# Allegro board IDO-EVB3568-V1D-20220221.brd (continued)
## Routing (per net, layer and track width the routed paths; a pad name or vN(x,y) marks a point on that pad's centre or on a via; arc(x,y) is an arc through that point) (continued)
GND_EARTH: length 535
  TOP w0.432: 136.01,89.17 J31.SH2 137.46,90.62
  GND w1.016: H2.1 9.02,0.89 94.74,0.89 96.01,2.16 100.08,2.16 101.35,0.89 135.92,0.89 H1.1 144.27,9.25 144.27,75.03 H4.1
  GND w1.524: H4.1 140.06,86.58 J31.SH2 J31.SH1 J30.SH2 J30.SH1
  BOTTOM w1.016: H2.1 9.02,0.89 94.74,0.89 96.01,2.16 100.08,2.16 101.35,0.89 135.92,0.89 H1.1 144.27,9.25 144.27,75.03 H4.1
  BOTTOM w1.524: H4.1 140.06,86.58 J31.SH2 J31.SH1 J30.SH2 J30.SH1
GND_IN: length 51.4
  TOP w0.432: 10.17,93.58 J2.2 ; J2.2 12.12,93.58 ; J2.2 11.14,95.26 ; J2.2 11.14,91.91 ; 18.19,88.21 J1.1 ; J1.1 19,87.4 ; J1.1 19.81,88.21 ; J1.1 19,89.03 ; 16.97,87.4 J1.2 ; J1.2 16.97,89.03 ; J1.2 16.15,88.21 ; J1.2 17.78,88.21 ; 4.97,93.58 J2.3 ; J2.3 5.94,95.26 ; J2.3 5.94,91.91 ; J2.3 6.92,93.58
  GND w0.432: 4.97,93.58 J2.3 ; J2.3 6.92,93.58 ; J2.3 5.94,91.91 ; J2.3 5.94,95.26 ; 16.97,87.4 J1.2 ; J1.2 16.97,89.03 ; J1.2 16.15,88.21 ; J1.2 17.78,88.21 ; 18.19,88.21 J1.1 ; J1.1 19,89.03 ; J1.1 19.81,88.21 ; J1.1 19,87.4 ; J2.2 12.12,93.58 ; J2.2 10.17,93.58 ; J2.2 11.14,91.91 ; J2.2 11.14,95.26
  BOTTOM w0.432: 16.97,87.4 J1.2 ; J1.2 17.78,88.21 ; J1.2 16.15,88.21 ; J1.2 16.97,89.03 ; 19,87.4 J1.1 ; J1.1 19.81,88.21 ; J1.1 18.19,88.21 ; J1.1 19,89.03 ; 11.14,91.91 J2.2 ; J2.2 11.14,95.26 ; J2.2 10.17,93.58 ; J2.2 12.12,93.58 ; J2.3 6.92,93.58 ; J2.3 4.97,93.58 ; J2.3 5.94,95.26 ; J2.3 5.94,91.91
  vias: v1(5.59,78.36) v1(5.59,77.6) v1(6.35,78.36) v1(6.35,77.6) v1(6.35,76.83) v1(6.35,76.07) v1(6.35,75.31) v1(7.11,77.6) v1(7.11,76.83) v1(7.11,76.07) v1(7.11,75.31) v1(7.87,77.34)
VBAT_RTC: length 15
  TOP w0.305: v1(134.11,32.82) 134.11,33.26 J40.2
  TOP w0.508: D93.A v1(123.57,37.2)
  BOTTOM w0.508: v1(134.11,32.82) 134.11,35.05 131.96,37.2 v1(123.57,37.2)
VBUSM: length 4.3
  BOTTOM w0.254: U8.41 82.13,55.89 R45.1
  BOTTOM w0.381: R44.1 R45.1
VCC1V5_DVP: length 4.9
  TOP w0.381: v2(27.05,60.07) 27.05,59.44 ; 27.05,59.44 27.15,59.44 27.58,59.87 v2(27.58,60.07) ; 27.05,59.44 26.42,58.8 J28.3 ; R388.2 C492.1 29.62,59.49 v1(29.97,59.84)
VCC1V8_DVP: length 0.9
  TOP w0.381: v1(24.77,59.64) 24.43,59.3 J28.4
VCC2V8_DVP: length 0.9
  BOTTOM w0.305: C152.2 R390.2
  vias: v2(27.3,56.26) v2(27.64,56.11) v2(27.64,55.7)
VCC3V3_PHY0: length 18.1
  TOP w0.152: R191.2 101.3,77.04 100.97,76.71 100.97,75.62 102.54,74.04 103.99,74.04 C188.2
  TOP w0.203: R196.2 v2(103.15,69.47) 103.15,69.98 R200.2
  TOP w0.381: C188.2 C187.2 104.28,72.54 v2(103.8,73.03) ; v1(110.36,73.3) C189.2 ; v1(110.36,73.3) 110.47,73.2 R218.1 ; v1(110.36,73.3) 110.54,73.48 110.82,73.48 v2(111.08,73.74)
  TOP w0.508: v2(104.97,67.74) 104.97,67.66 C190.2
  BOTTOM w0.203: 105.15,67.89 105.18,67.89 105.43,68.14 U24.29 ; 105.03,67.8 105.06,67.8
  BOTTOM w0.254: v2(104.97,67.74) 105.03,67.8 ; U24.11 109.7,72.67 110.34,73.3 v1(110.36,73.3) ; U24.40 104.16,72.67 v2(103.8,73.03)
  BOTTOM w0.305: 105.06,67.8 105.15,67.89
  BOTTOM w0.508: v1(110.36,73.3) 110.39,73.28 C191.2 v2(111.08,73.74) 111.35,74.02 111.35,74.09 R229.2
VCC3V3_PHY1: length 19.6
  TOP w0.305: C212.2 118.14,66.73 118.14,66.37 118.39,66.11 118.75,66.11
  TOP w0.381: C214.2 118.42,72.54 118.21,72.34 118.21,71.85 v2(118.11,71.75) C215.2 ; C213.2 125.64,71.66 125.64,72.2 125.63,72.21 v1(125.63,72.24) R277.2 ; C216.2 123.6,71.75 v2(123.62,71.73) 123.71,71.64 124.25,71.64 124.28,71.68 R266.1 ; R243.2 117.55,66.5 117.93,66.88 118.24,66.88 118.41,66.7 118.41,66.45 v2(118.77,66.09)
  VCC w0.203: 117.5,73.41 117.4,73.41 116.76,72.77 116.05,72.77 115.14,73.69 115.14,74.78 114.2,75.72 113.06,75.72 v2(112.93,75.59)
  BOTTOM w0.203: R247.2 112.93,74.76 v2(112.93,75.59) 112.72,75.59 R238.2 ; 118.78,66.08 v2(118.77,66.09)
  BOTTOM w0.254: v2(123.62,71.73) 123.62,71.17 123.44,70.99 U25.11 ; U25.29 119.45,66.52 119.41,66.47 119.41,66.38 119.1,66.08 119.07,66.08 ; U25.40 118.11,71.38 v2(118.11,71.75)
  BOTTOM w0.305: 119.07,66.08 118.78,66.08
VCC3V3_SD: length 49.8
  TOP w0.508: M5.69 94.67,35.24 93.34,33.91 v1(93.34,31.24) ; J3.4 125.63,16.06 125.7,16.13 D2.1 125.7,17.63 125.92,17.84 C35.2 125.92,18.73 125.41,19.24 v1(125.41,19.24)
  BOTTOM w0.508: v1(125.41,19.24) 125.41,20.13 122.68,22.86 120.02,22.86 113.67,29.21 113.67,29.84 113.16,30.35 107.31,30.35 105.92,31.75 103.25,31.75 102.36,30.86 94.36,30.86 93.98,31.24 v1(93.34,31.24)
VCC5V0_SYS: length 214.3
  TOP w0.203: R309.1 21.95,32.84 21.95,35.1 22.25,35.41 R306.1
  TOP w0.254: R13.1 C24.2 v1(26.42,53.85)
  TOP w0.381: v1(77.85,8.89) 77.85,8.08 78.21,7.72
  TOP w0.508: v1(21.34,37.47) 21.03,37.16 C236.2 20.3,36.85 19.94,37.21 U33.3 ; J34.4 10.16,60 ; R306.1 v1(22.93,35.99)
  TOP w0.762: J36.4 9.05,34.09 9.63,34.67 ; v1(75.39,52.83) 75.39,45.16 70.48,40.26 64.95,40.26 64.19,39.5 54.51,39.5 53.75,38.73 v1(53.75,38.51) ; 10.54,47.04 10.54,48.63 v1(8.88,50.29) 10.44,51.85 10.44,59.72 10.16,60 10.31,60.15 10.31,72.92 10.34,72.95 ; 10.54,47.04 J35.4 ; 10.54,47.04 10.54,39.62 10.19,39.27 ; 10.34,72.95 v1(10.59,73.2) 10.97,73.2 v1(11.3,73.53) 11.46,73.69 11.46,84.51 10.06,85.91 J32.4 ; 10.34,72.95 J33.4
  TOP w1.016: J20.3 84.04,7.72 78.21,7.72 75.95,5.46 56.64,5.46 54.36,7.75 50.29,7.75 49.34,8.7 J25.3
  BOTTOM w0.203: 48.56,35.46 48.95,35.46 49.84,34.57 R7.1
  BOTTOM w0.381: v1(84.2,19.43) 84.32,19.55 Q17.1 85.73,19.55 85.8,19.48 R380.1 ; v1(75.39,52.83) 75.9,52.32 78.74,52.32 80.01,53.59 R44.2 ; v1(73.53,12.45) 76.96,12.45 77.85,11.56 v1(77.85,8.89) ; v1(26.42,53.85) 26.42,43.48 27.36,42.55 v1(29.97,42.55)
  BOTTOM w0.508: v1(75.39,52.83) 75.39,53.53 L13.1 ; D83.A v1(8.88,50.29)
  BOTTOM w0.762: v1(11.3,73.53) 10.97,73.2 v1(10.59,73.2) ; v1(53.75,38.51) 53.7,38.51 52.81,37.62 52.81,31.72 v1(52.2,31.11)
  BOTTOM w1.016: v1(78.05,24.64) v1(78.05,22.35) 78.05,21.44 79.12,20.38 79.12,16.76 85.46,10.43 J20.3
  vias: v1(15.98,26.95) v1(16.23,27.48) v1(16.51,26.49) v1(21.08,43.31) v1(21.26,42.75) v1(21.62,43.15) v1(29.95,42.01) v1(29.95,41.48) v1(30.51,42.55) v1(30.48,42.01) v1(30.48,41.48) v1(31.04,42.55) v1(31.01,42.01) v1(31.01,41.45) v1(33.99,15.19) v1(34.52,15.16) v1(38.48,26.04) v1(38.48,25.4) v1(38.48,24.77) v1(39.06,26.08) v1(39.12,25.4) v1(39.12,24.77) v1(46.61,36.07) v1(47.12,35.31) v1(47.88,36.07) v1(47.88,35.31) v1(104.39,22.35) v2(104.27,21.72) v2(104.8,21.72) v2(110.36,39.88) v2(110.36,39.37) v2(110.87,39.88) v2(110.87,39.37) v2(111.38,39.88) v2(111.38,39.37)
VCC5V0_USB_FE_D1: length 0.8
  TOP w1.016: J8.10 73.76,87.91
VCC5V0_USB_FE_D2: length 2.7
  TOP w0.432: 91.37,91.34 J9.1 ; J9.1 92.04,92.02 ; J9.1 92.04,90.66 ; J9.1 92.72,91.34
  vias: v1(90.63,83.08) v1(91.21,82.96) v1(91.26,82.42)
VCC5V0_USB_FE_D3: length 1.2
  TOP w1.016: J9.10 92.04,87.53
VCC5V0_USB_FE_D4: length 2.4
  TOP w0.432: 142.09,44.78 J10.1 ; J10.1 142.9,45.59 ; J10.1 141.27,45.59
VCC5V0_USB_FE_D5: length 2.4
  TOP w0.432: 141.17,56.24 J11.1 ; J11.1 142.8,56.24 ; J11.1 141.99,55.42
VCC5V0_USB_FE_D6: length 2.4
  TOP w0.432: 141.96,65.96 J12.1 ; J12.1 142.77,66.78 ; J12.1 141.15,66.78
VCC5V0_USB_HOST1: length 3.6
  TOP w0.432: 53.36,89.31 J5.10 54.1,90.04
  TOP w0.635: 54.79,88.95 54.43,89.31 ; 54.43,89.31 54.83,89.31 ; 54.43,89.31 J5.10 54.1,89.02 53.64,88.57
VCC5V0_USB_HOST3: length 1.4
  BOTTOM w0.432: 73.76,92.02 J8.1 73.08,91.34
VCC5V0_USB_OTG0: length 3.6
  BOTTOM w0.635: 54.1,92.55 J5.1 54.18,92.51 ; 54.1,92.55 54.1,93.24 ; 54.1,92.55 54.64,93.09 ; 54.18,92.51 54.83,92.51 ; 54.18,92.51 54.53,92.15 55.42,92.15
VCC5V_HDMI_TX: length 14.2
  TOP w0.305: J18.18 33.65,94.06 33.95,94.36 34.87,94.36 35.18,94.06
  TOP w0.508: 35.18,94.06 35.18,91.57 36.19,90.55 38.61,90.55 40.69,88.47 C96.2 40.69,87.45 40.77,87.38 D51.C
VCC12V_DC_IN: length 11
  BOTTOM w0.432: J1.3 14.94,89.03 ; J1.3 14.94,87.4 ; J1.3 14.12,88.21 ; 12.9,87.4 J1.4 ; J1.4 12.09,88.21 ; J1.4 13.72,88.21 ; J1.4 12.9,89.03 ; 1.56,93.58 J2.4 ; J2.4 3.52,93.58 ; J2.4 2.54,91.91 ; J2.4 2.54,95.26
VCC12V_DCIN: length 22.9
  TOP w0.254: R3.1 C23.2 24.89,49.66 25.12,49.42 U39.1
  VCC w1.016: 51.18,3.68 51.28,3.78 J27.5 J27.6 ; J21.6 89.41,3.68 ; J21.6 89.41,7.71 89.46,7.76 J20.1 ; J21.6 J21.5 87.4,3.71 87.38,3.68 ; J25.1 53.34,7.76 53.29,7.71 J27.6 ; J27.6 53.29,3.63 53.21,3.56
  vias: v1(5.33,10.03) v1(5.33,9.27) v1(6.1,10.03) v1(6.1,9.27) v1(6.86,10.03) v1(6.86,9.27) v1(7.62,9.27) v1(8.76,4.45) v1(9.53,5.21) v1(9.53,4.45) v1(10.29,5.21) v1(10.29,4.45) v1(11.05,4.45) v1(22.35,76.07) v1(22.35,75.31) v1(23.11,76.07) v1(23.11,75.31) v1(23.88,76.07) v1(23.88,75.31) v1(23.98,48.84) v1(24.46,48.92) v1(24.64,76.07) v1(24.64,75.31) v1(24.79,48.34) v1(24.77,47.65) v1(24.99,48.97) v1(25.4,76.07) v1(25.4,75.31) v1(61.04,88.42) v1(61.04,87.91) v1(61.06,88.9) v1(61.44,89.26) v1(61.44,88.19) v1(61.44,87.66) v1(61.47,88.72)
VCC_1V8: length 209
  TOP w0.254: v2(131.06,43.69) 131.14,43.61 R61.1 R60.1
  TOP w0.381: v2(104.01,58.57) 104.06,58.52 R172.1
  TOP w0.508: v1(83.19,50.36) 82.74,50.8 78.23,50.8 77.34,49.91 77.34,30.99 75.69,29.34 70.23,29.34 69.34,28.45 v1(68.07,28.45) ; v1(100.08,55.37) 100.28,55.58 v1(100.28,59.44) 100.28,61.39 97.36,64.31 97.36,68.76 96.21,69.9 M5.103
  VCC w0.381: v2(120.07,42.61) 119.65,42.61 119.35,42.9 116.12,42.9 v2(116.07,42.95)
  BOTTOM w0.254: v2(116.07,42.95) 111.99,42.95 110.62,44.32 98.93,44.32 98.34,44.91 97.66,44.91 97.21,44.45 97.21,43.81
  BOTTOM w0.508: v1(100.08,55.37) 96.9,55.37 96.01,54.48 96.01,50.04 ; 96.01,50.04 95.89,49.91 86.61,49.91 86.17,50.36 v1(83.19,50.36) ; 96.01,50.04 96.01,44.58 96.77,43.81 97.21,43.81 97.2,43.81 R146.2 R147.2 ; v2(120.07,42.61) 120.35,42.61 130.11,42.61 131.06,43.56 v2(131.06,43.69) ; v2(104.01,58.57) 102.34,58.57 101.47,59.44 v1(100.28,59.44) ; v1(11.43,13.59) v1(11.94,13.08) 13.97,11.05 28.83,11.05 29.34,11.56 45.85,11.56 47.5,13.21 52.81,13.21 53.95,12.06 54.86,12.06 55.71,11.21 70.52,11.21 71.5,12.19 71.5,14.98 70.6,15.88 70.05,15.88 68.96,16.97 68.96,22.35 69.72,23.11 69.72,26.8 v1(68.07,28.45)
  vias: v1(92.71,72.39) v1(93.22,72.01)
VCC_1V8_HUB: length 34
  TOP w0.508: v1(75.44,61.09) 76.41,60.12 v1(78.49,60.12) ; v2(86.87,67.67) 86.79,67.74 82.8,67.74 v2(82.7,67.64) ; v2(87.25,63.83) 86.84,64.24 86.51,64.24 v1(85.66,65.09) 84.09,65.09 83.9,64.9 v2(83.31,64.9)
  BOTTOM w0.254: U8.28 86.53,63.12 87.24,63.83 v2(87.25,63.83) 87.41,64 87.41,64.3 87.91,64.8 C74.2 ; C75.2 75.14,61.39 v1(75.44,61.09) 75.98,61.63 U8.6 ; v1(85.66,65.09) U8.25
  BOTTOM w0.305: U8.21 82.63,67.57 v2(82.7,67.64)
  BOTTOM w0.381: C76.2 82.7,67.97 v2(82.7,67.64)
  BOTTOM w0.508: v1(85.66,65.09) 86.36,65.8 86.36,67.16 v2(86.87,67.67) 87.4,68.2 C63.2 ; v1(78.49,60.12) 81.84,60.12 83.31,61.59 v2(83.31,64.9)
VCC_3V3: length 79.6
  TOP w0.203: M5.104 93.39,70.86 91.09,73.15 89.15,73.15 88.18,74.13 72.81,74.13 72.29,74.65 70.4,74.65 70.12,74.93 69.6,74.93 69.34,74.68 66.32,74.68 v1(65.28,73.63) ; v2(56.92,58.9) 55.88,58.9 55.45,58.47 54.53,58.47 52.83,56.77 v2(36.58,56.77) ; v2(33.53,56.52) 32.77,55.75 v2(32.77,51.82)
  BOTTOM w0.203: v2(36.58,56.77) 35.81,56.77 35.56,56.52 v2(33.53,56.52) ; v2(56.92,58.9) 57.07,58.9 65.28,67.11 v1(65.28,73.63) ; R14.1 v2(32.77,51.82)
VCC_3V3_HUB: length 34.9
  TOP w0.508: v1(78.11,67.72) v2(79.63,67.72) 81.89,67.72 v2(82.07,67.54)
  BOTTOM w0.254: v2(87.48,61.7) 87.41,61.63 U8.31 ; U8.42 81.63,56.1 80.9,55.37 v1(78.99,55.37)
  BOTTOM w0.279: v2(86.77,65.02) 86.77,64.41 86.48,64.12 U8.26
  BOTTOM w0.305: U8.20 82.13,67.48 v2(82.07,67.54) ; U8.15 v2(79.63,67.72) ; v1(75.48,63.25) 75.6,63.12 U8.9
  BOTTOM w0.381: v2(79.63,67.72) 79.63,68.1 C71.2 ; R48.1 83.06,52.98 82.78,52.7 v2(80.01,52.7) ; C73.2 81.99,67.79 82.07,67.72 v2(82.07,67.54) ; v2(87.48,61.7) C69.2
  BOTTOM w0.508: v2(86.77,65.02) 86.77,65.3 87.12,65.66 87.12,66.09 C72.2 ; C59.2 74.72,64.01 v1(75.48,63.25) ; R46.2 C68.2 77.98,53.53 v1(78.23,53.28) ; C70.2 v1(78.99,55.37) ; v1(78.11,67.72) 78.11,65.15 78.99,64.26 v1(78.99,61.72)
  vias: v2(83.97,59.05) v2(84.2,59.44) v2(84.5,59.05) v2(87.63,58.17) v2(88.14,58.17)
VCC_3V8: length 16.8
  TOP w0.254: v2(127.64,21.21) 130.56,21.21 130.94,20.83 R334.1
  TOP w0.381: C246.2 102.87,38.3 102.49,38.68 102.49,41.78 104.19,43.48 R340.1 C265.2
  BOTTOM w0.254: R337.1 125.94,35.15 C483.2
  vias: v1(104.9,35.31) v1(104.9,34.59) v1(104.9,33.91) v1(105.54,34.54) v1(105.58,35.31) v1(105.6,33.91) v1(108.55,32.59) v1(127.89,30.1) v2(118.24,36.58) v2(118.24,36.07) v2(118.75,36.58) v2(118.75,36.07) v2(124.71,36.58) v2(124.71,36.07) v2(125.22,36.54) v2(125.22,36.01) v2(126.49,21.59) v2(126.87,21.21) v2(127.25,21.59) v2(128.01,31.6) v2(128.09,32.13) v2(128.63,32.13) v2(128.65,31.62) v2(129.16,32.13) v2(129.16,31.6)
VCC_5V_HUB: length 11.2
  BOTTOM w0.254: U8.8 75.96,62.62
  BOTTOM w0.381: C58.2 75.95,62.61 75.96,62.62
  BOTTOM w0.508: C58.2 74.49,62.54 73.91,61.96 73.91,60.2 75.56,58.55 L13.2
VCC_485: length 4
  TOP w0.381: C232.2 12.52,46.1 U31.8 ; v2(12.32,51.31) C228.2 12.83,51.97 13.06,51.74 U29.8
  vias: v2(11.51,49.28) v2(12.04,49.28) v2(12.57,49.28)
VCC_EDP_OUT: length 6
  TOP w1.016: 83.46,11.16 J20.4 ; 79.46,11.13 J20.6 ; J20.2 87.46,11.09
VCC_EDP_OUT_: length 6.2
  TOP w1.016: C112.2 75.69,10.92 75.29,10.52 J19.1 J19.2
VCC_LEDA_TX0: length 0.8
  TOP w0.381: v1(14.5,24.89) U15.5
  vias: v1(16.74,29.16) v1(17.04,28.73) v1(17.25,29.18)
VCC_LEDA_TX1: length 11
  TOP w0.381: v1(46.1,26.54) 46.1,31.27 v1(42.37,35)
  BOTTOM w0.381: U16.5 v1(42.37,35)
VCC_LEDK_TX0: length 7.9
  TOP w0.203: R104.2 13.21,21.95 v1(13.21,21.95)
  BOTTOM w0.203: v1(13.21,21.95) 13.28,21.87 13.28,21.64 14.55,20.37 18.52,20.37 18.79,20.64 J22.9
VCC_LEDK_TX1: length 11.6
  TOP w0.508: v1(41.4,30.23) 45.77,25.86 47.19,25.86 v1(47.88,26.54)
  BOTTOM w0.508: R115.2 39.19,30.6 39.57,30.23 v1(41.4,30.23)
VCC_SIM: length 36
  TOP w0.305: U36.36 117.94,29.26 118.25,28.96
  TOP w0.508: v1(109.86,36.7) 109.86,37.86 ; 109.86,37.86 109.35,38.37 L48.2 ; 109.86,37.86 110.14,38.15 R339.2 ; 118.25,28.96 122.3,28.96 123.06,29.72 v1(123.06,32.26) 122.56,32.77 v1(116.08,32.77)
  BOTTOM w0.508: SIM1.C1 124.64,30.66 123.6,31.69 D97.1 ; v1(109.86,36.7) 113.16,36.7 113.92,35.94 R330.2 115.39,34.47 116.08,33.78 v1(116.08,32.77) ; C260.2 C261.2 123.65,32.31 D97.1 ; v1(123.06,32.26) D97.1
VCCA_CODEC: length 11.4
  TOP w0.508: C94.2 97.54,15.37 v1(97.41,15.49)
  BOTTOM w0.508: L22.2 94.4,21.38 94.54,21.52 C95.2 95.25,21.01 95.2,20.95 U13.9 95.2,18.72 96.39,17.53 96.39,16.51 v1(97.41,15.49) 97.74,15.16 U13.6
VCCIO_ACODEC: length 60.6
  TOP w0.305: v1(133.73,21.64) R75.1
  TOP w0.508: v1(91.95,15.75) 91.95,16.04 L16.2 92.96,16.38 92.96,15.8 93.14,15.62 R69.2
  BOTTOM w0.508: v1(91.95,15.75) 91.95,13.34 91.44,12.83 91.44,10.94 94.63,7.75 102.62,7.75 104.65,9.78 125.48,9.78 132.72,17.02 132.72,20.62 v1(133.73,21.64)
VCCIO_PHY0: length 32.5
  TOP w0.381: C184.2 105.16,68.43 105.66,67.93 105.66,67.78 v2(105.68,67.76)
  TOP w0.508: v1(110.36,70.89) 110.35,70.88 109.53,70.88 109.51,70.9 109.42,70.9 C185.2 108.99,71.32 R220.2 108.88,72.26 108.37,72.77 108.37,74.04 108.36,74.05 108.36,74.08 108.02,74.42 107.99,74.42 107.86,74.55 102.84,74.55 101.63,75.77 v1(101.63,75.92) ; v1(93.22,76.2) 97.05,76.2 97.18,76.33 v1(97.83,76.33)
  GND w0.508: v1(110.36,70.89) 110.08,70.89 108.05,68.86 106.53,68.86 105.69,68.02 105.69,67.76 v2(105.68,67.76)
  BOTTOM w0.203: U24.28 105.83,68.12 105.76,68.05 105.76,68.01 105.71,67.96 105.71,67.89 105.69,67.86 105.69,67.76 v2(105.68,67.76)
  BOTTOM w0.508: v1(93.22,76.2) 93.22,75.64 92.71,75.14 C183.2 ; R222.2 C183.2 ; C183.2 R221.2 ; v1(101.63,75.92) 101.22,76.33 v1(97.83,76.33)
VCCIO_PHY1: length 55.1
  TOP w0.381: C208.2 119.33,66.8 119.33,66.77 119.83,66.27 v2(119.85,66.27) 119.31,65.73
  TOP w0.508: v1(90.3,75.44) 95.38,75.44 101.47,69.34 101.47,67.56 102.97,66.07 R209.2 R211.2 R214.2 R217.2 R207.2 C210.2 111.78,66.07 112.06,65.79 114.3,65.79 115.57,64.52 118.1,64.52 118.74,65.16 ; 118.74,65.16 119.31,65.73 ; 118.74,65.16 119.25,64.64 R258.2 R261.2 R264.2 R251.2 124.84,64.64 126.01,65.81 126.01,69.32 v2(126.24,69.55)
  BOTTOM w0.203: R255.2 118.7,65.46 118.9,65.66 119.24,65.66 v2(119.85,66.27)
  BOTTOM w0.254: v2(119.85,66.27) U25.28
  BOTTOM w0.381: v2(126.24,69.55) 125.91,69.88 R268.2
  BOTTOM w0.508: C209.2 v1(90.3,75.44) ; C209.2 R270.2 ; C209.2 R269.2
VCCIO_WL: length 171.7
  TOP w0.254: v2(123.01,56.06) 123.56,55.51 Q11.1
  TOP w0.305: Q15.1 23.38,33.79 v2(23.5,33.91)
  TOP w0.508: v1(117.47,61.59) 117.47,63.5 117.38,63.6 117.38,63.61 117.16,63.83 117.14,63.83 117.09,63.88 115.19,63.88 113.97,65.1 R157.1 112.49,65.1 112.47,65.07 R152.1 108.79,65.07 108.43,65.43 101.95,65.43 101.5,65.89 ; R166.1 C161.2 R171.2 v2(120.78,56.06) ; U23.22 v1(106.9,59.08) ; v1(78.16,76.3) 78.44,76.58 88.01,76.58 89.92,74.68 95,74.68 100.58,69.09 100.58,66.74 101.36,65.96 101.42,65.96 101.5,65.89 ; 101.5,65.89 101.5,63.86 102.54,62.81 v1(102.54,59.44) 102.54,58.6 103.2,57.94 R172.2 R176.1 ; v1(39.22,62.97) 39.64,62.55 65.7,62.55 69.07,65.91 v1(75.69,65.91)
  BOTTOM w0.254: R305.1 22.48,36.76 22.23,36.5 22.23,34.16 22.53,33.86 R308.1
  BOTTOM w0.381: R308.1 23.45,33.86 v2(23.5,33.91)
  BOTTOM w0.508: v1(39.22,62.97) 38.75,62.5 38.75,46.5 31.37,39.12 26.16,39.12 23.8,36.76 R305.1 ; v2(123.01,56.06) v2(120.78,56.06) 118.44,56.06 117.47,57.02 v1(117.47,61.59) ; v1(102.54,59.44) 102.77,59.21 103.86,59.21 103.89,59.23 C163.2 C162.2 106.76,59.23 v1(106.9,59.08) ; v1(78.16,76.3) 78.16,76.07 76.23,74.14 76.23,69.55 75.69,69.01 v1(75.69,65.91)
VDD10_PHY0: length 5.3
  TOP w0.305: v2(103.88,71.92) 103.9,71.89 104.03,71.89 104.42,71.5 C181.2
  TOP w0.381: C175.2 109.48,68.58 109.07,68.58 v2(109.06,68.59) ; v2(107.78,73.83) 107.44,73.5 C178.2 ; C180.2 106.38,73.4 v2(105.88,73.9)
  BOTTOM w0.203: U24.3 105.83,73.85 v2(105.88,73.9) ; U24.8 107.83,73.78 v2(107.78,73.83) ; v2(109.06,68.59) 108.99,68.52 U24.21 ; U24.38 103.93,71.87 v2(103.88,71.92)
  vias: v2(98.02,67.79) v2(98.02,67.18) v2(98.4,68.68) v2(98.43,68.15) v2(98.47,67.47)
VDD10_PHY1: length 5.7
  TOP w0.381: C204.2 118.26,69.85 v2(117.87,70.24) ; C199.2 121.79,72.06 v2(121.85,72.12) ; v2(119.85,72.17) 119.86,72.16 C205.2 ; v2(123.52,66.27) 123.72,66.27 C201.2
  BOTTOM w0.254: U25.3 v2(119.85,72.17) ; U25.38 117.92,70.19 v2(117.87,70.24) ; v2(123.52,66.27) 123.52,66.29 122.97,66.84 U25.21 ; U25.8 v2(121.85,72.12)
  vias: v2(113.79,66.42) v2(114.3,66.85) v2(114.3,66.42)
VDD_3V3: length 247.8
  TOP w0.254: v2(61.09,13.21) 61.17,13.13 R374.1
  TOP w0.305: R300.1 11.58,45.29 v2(11.35,45.52) ; R87.1 R81.1 34.04,82.87 Q3.1 34.04,84.87 34.26,85.09 35.94,85.09 36.2,84.83 Q4.1 36.2,83.43 36.27,83.36 R83.1 ; D92.A 120.85,40.01 119.48,41.38 119.48,43.03 120.35,43.89 v2(121.67,43.89)
  TOP w0.381: v2(116.06,43.55) 115.73,43.55 R313.2 ; v2(94.61,40.89) 94.61,41.53 93.87,42.28 93.87,45.47 93.98,45.58 v2(93.98,46.1) ; U27.16 20.18,63.54 v2(20.19,63.55) 20.27,63.63 C222.2 ; R171.1 122.35,55.7 122.94,55.12 123.32,55.12 123.7,54.74 v2(126.49,54.74) ; R25.1 102.14,18.16 102.12,18.14 99.57,18.14 97.97,19.74 v2(92.71,19.74) ; v2(79.63,38.61) 79.63,39.77 v2(78.89,40.51) v2(78.89,41.66) ; R126.1 36.62,13.15 37.06,13.59 v1(37.47,13.59) ; v2(95.25,17.53) R72.1 ; U26.16 20.23,70.25 20.34,70.36 C217.2 v2(20.91,70.99) ; R312.2 122.1,44.27 121.71,43.89 v2(121.67,43.89)
  TOP w0.508: v1(70.74,16.64) 70.48,16.38 67.2,16.38 v1(66.65,16.93) ; R174.1 125.67,63.99 126.97,65.3 126.97,69.88 126.36,70.48 126.36,73.05 125.86,73.56 R277.1 125.17,73.56 124.82,73.2 121.92,73.2 121.39,73.74 116.89,73.74 v1(116.46,74.17) ; R83.1 v1(36.27,82.12) ; v1(83.19,49.54) 80.32,49.54 v1(80.31,49.53) ; v2(81.41,22.2) v2(82.04,22.2) 91.97,22.2 v2(92.08,22.1) v2(92.58,22.1)
  TOP w1.016: C107.2 57.61,12.18 57.61,11.7 57.29,11.38 J19.19
  BOTTOM w0.203: 65.21,41.15 65.41,40.94 U35.8 ; C243.2 68.4,39.96 68.26,39.81 U35.13
  BOTTOM w0.254: R323.1 65.38,42.72 64.52,41.86 64.29,41.86 ; R9.1 23.62,80.52 24,80.14 26.04,80.14 28.32,77.85 28.32,76.71
  BOTTOM w0.305: C124.2 76.96,23.62 76.45,23.11 75.69,23.11 75.32,22.74 J24.6
  BOTTOM w0.381: v2(78.89,41.66) R356.2 ; 76.07,28.57 76.07,24.38 76.77,23.68 C124.2 ; 81.31,47.88 82.41,46.78 U38.24 ; R302.2 22.53,44.78 22.1,45.21 19.81,45.21 19.56,45.47 19.56,46.23 20.24,46.91 C231.2 ; v2(71.37,73.42) R165.1 ; R358.2 v2(78.89,40.51) ; v2(79.63,38.61) 79.45,38.78 R361.2 ; v2(80.8,75.1) 80.8,73.48 R110.2 ; R109.2 v2(78.49,75.1) ; 65.21,41.15 65,41.15 64.29,41.86 C244.2 ; R287.1 v1(21.41,54.18)
  BOTTOM w0.508: C244.2 C242.2 ; 67.94,31.83 67.94,29.59 70.48,27.05 70.48,22.73 69.72,21.97 69.72,17.14 70.23,16.64 v1(70.74,16.64) 74.04,13.34 79.12,13.34 81.46,11 J20.5 ; R360.2 R359.2 R357.2 77.17,48.47 78.23,49.53 v1(80.31,49.53) C268.2 81.31,47.88 ; v2(94.61,40.89) 93.73,40.01 R346.2 R347.2 ; 68.71,34.8 68.66,34.75 R322.2 R318.2 ; v1(116.46,74.17) 113.54,77.09 111.91,77.09 111.51,76.68 R229.1 ; 28.7,76.45 30.1,77.85 35.77,77.85 36.27,78.36 v1(36.27,82.12) ; R364.1 79.38,43.77 R354.2 R355.2 R356.2 ; 35.31,52.32 35.23,52.4 32.26,52.4 31.75,51.89 C19.2 R12.1 ; R348.2 R349.2 R350.2 R351.2 R352.2 R353.2 v2(93.98,46.1) 94.87,46.1 95.3,46.53 R362.1 R363.1 95.3,48.77 94.92,49.15 86.11,49.15 85.71,49.54 v1(83.19,49.54)
  BOTTOM w1.016: J25.5 46.99,10.79 54.36,10.79 56.01,9.14 J19.19
  vias: v1(18.03,52.96) v1(18.92,70.87) v1(19.68,70.87) v1(20.07,50.93) v1(20.38,71.29) v1(21.46,71.25) v1(37.08,58.93) v1(37.08,58.29) v1(37.72,58.93) v1(37.72,58.29) v1(55.63,13.97) v1(56.39,13.97) v1(61.85,41.78) v1(61.85,41.02) v1(62.57,41.78) v1(62.61,41.02) v1(70.74,59.82) v1(70.74,59.05) v1(71.5,59.82) v1(71.5,59.05) v1(91.12,71.9) v1(91.27,71.21) v1(91.76,71.68) v1(125.81,54.1) v1(126.49,54.1) v1(126.62,62.99) v1(126.62,62.31) v1(126.62,61.64) v1(127.25,61.21) v2(60.83,40.89) v2(87.26,55.54) v2(87.38,55.09) v2(87.79,55.5) v2(94.23,17.53) v2(94.74,17.53) v2(94.74,17.02) v2(127.2,63.27) v2(127.81,63.27)
VDD_RTC: length 7.9
  TOP w0.305: D92.C 120.41,39.37 122.44,39.37 D93.C
  TOP w0.381: D92.C 117.93,40.01 C241.2 118.04,39.98 118.59,40.53 118.59,41.07 118.32,41.34 U34.8
VDD_USB_5V: length 39.8
  TOP w0.305: v1(68.86,79.02) 68.86,81.31 67.61,82.55 R4.1 C8.2
  TOP w0.508: v1(40.77,84.2) D51.A D49.A ; Q5.1 31.89,84.46 v1(32.38,84.96)
  VCC w0.432: 142.01,11.15 J14.1 ; J14.1 141.2,11.96 ; J14.1 142.82,11.96 ; J14.1 142.01,12.78
  VCC w0.508: v1(50.42,79.86) v1(49.96,80.32) 49.96,80.85 v1(46.04,84.77)
  BOTTOM w0.432: 71.98,75.67 J7.1 71.98,77.55
  BOTTOM w0.508: J7.1 71.04,77.55 ; J7.1 70.76,76.61 ; J7.1 71.04,75.67 ; v1(32.38,84.96) 33.15,84.2 v1(40.77,84.2) 42.04,85.47 45.34,85.47 v1(46.04,84.77)
  vias: v1(56.69,83.26) v1(56.79,81.33) v1(57.23,83.85) v1(57.23,83.31) v1(57.23,82.75) v1(57.23,82.25) v1(57.2,81.71) v1(81.99,82.88) v1(83.24,82.96) v1(83.72,82.93) v1(84.23,82.93) v1(84.8,82.95) v1(96.65,82.04) v1(97.41,82.04) v1(133.07,44.2) v1(133.31,62.1) v1(133.48,52.2) v1(133.86,44.19) v1(133.99,62.1) v1(134.15,52.2)
4G_5G_RESET_: length 21.1
  TOP w0.127: v2(114.55,32.89) 114.55,34.92 115.82,36.2 Q16.3 115.82,37.58 116.35,38.1 116.72,38.1 117.02,38.4 R376.2 ; v2(116.33,29.08) 111.12,23.88 110.34,23.88 110.19,23.73 U36.67
  BOTTOM w0.127: v2(116.33,29.08) 116.33,29.72 114.55,31.5 v2(114.55,32.89)
4G_5G_RESET_GPIO3_A4: length 93
  TOP w0.127: v2(113.93,32.89) 113.93,35.19 115.19,36.45 115.19,37.64 115.9,38.35 116.08,38.35 116.32,38.6 Q16.1 ; M5.123 74.39,70.44 73.58,71.25 67.94,71.25 v2(67.69,71.5)
  BOTTOM w0.127: v2(67.69,71.5) 67.69,65.28 74.42,58.55 74.42,40.64 76.96,38.1 80.9,38.1 81.28,38.48 82.17,38.48 86.49,34.16 96.77,34.16 97.04,34.43 97.78,34.43 98.93,33.27 106.81,33.27 108.33,31.75 113.42,31.75 113.93,32.26 v2(113.93,32.89)
4G_LED_WANN#: length 25.7
  TOP w0.127: v2(126.75,36.58) 126.47,36.3 126.27,36.3 125.45,35.48 J41.42
  TOP w0.254: LED2.C 131.7,20.74 131.44,20.99 v1(131.44,21.59)
  BOTTOM w0.254: v2(126.75,36.58) 131.57,36.58 133.1,35.05 133.1,23.24 v1(131.44,21.59)
BT_REG_ON: length 44.9
  TOP w0.127: v2(77.8,74.82) 77.91,74.7 88.65,74.7 89.43,73.91 94.26,73.91 99.82,68.35 99.82,63.12 101.22,61.72 101.22,55.12 101.98,54.36 101.98,53.34 103.18,52.14 R161.1 R181.1
  BOTTOM w0.127: R160.2 77.47,74.45 77.8,74.78 v2(77.8,74.82)
BT_REG_ON_H_GPIO3_A7: length 4.1
  TOP w0.127: v2(77.39,69.22) M5.120
  BOTTOM w0.127: v2(77.39,69.22) 77.47,69.3 R160.1
BT_WAKE_HOST: length 10.8
  TOP w0.127: Q11.2 123.58,56.51 123.32,56.77 119.89,56.77 119.2,56.09 R170.2 R166.2 118.78,54.61 118.23,55.15 U23.7
BT_WAKE_HOST_H_GPIO3_A1: length 84.4
  TOP w0.127: v2(120.02,55.24) 120.02,56.01 R170.1 120.52,56.52 123.19,56.52 123.7,56.01 Q11.3 ; M5.126 71.39,69.44 v2(71.73,69.1) 72.63,68.2 87.12,68.2 87.63,67.69 92.71,67.69 v2(92.96,67.44) ; v2(117.86,65.79) 117.65,65.58 116.03,65.58 114.96,66.65 114.96,67.41 113.54,68.83 113.54,73.89 111.87,75.56 103.66,75.56 103.15,76.07 103.15,76.58 v2(102.13,77.6)
  BOTTOM w0.127: R165.2 71.37,69.46 v2(71.73,69.1) ; v2(120.02,55.24) 118.11,55.24 116.97,56.39 116.97,63.5 118.26,64.8 118.26,65.38 v2(117.86,65.79) ; v2(102.13,77.6) 96.72,77.6 95.63,76.5 95.63,70.87 92.96,68.2 v2(92.96,67.44)
CAN1_H: length 2.5
  TOP w0.152: v1(14.76,41.05) 14.22,41.58 U32.7
  BOTTOM w0.152: v1(14.76,41.05) 14.76,41 15.67,40.09 L46.1
CAN1_L: length 3
  TOP w0.152: U32.6 14.43,42.85 15.11,42.16 15.11,41.76 v1(15.29,41.58)
  BOTTOM w0.152: L46.2 15.54,41.21 15.54,41.33 v1(15.29,41.58)
CAN1_RX_M0: length 123.7
  TOP w0.127: v2(22.25,39.88) 20.19,39.88 19.58,39.27 18.24,39.27 17.63,38.66 17.63,34.16 15.67,32.21 12.04,32.21 11.77,31.94 11.77,26.76 11.05,26.04 11.05,17.6 10.59,17.14 10.59,16.69 v2(10.16,16.26) ; v2(69.09,25.53) 71.2,25.53 72.06,24.67 72.06,24.32 72.39,23.99 M5.36
  BOTTOM w0.127: v2(22.25,39.88) 22.25,41.45 21.42,42.28 20.86,42.28 20.4,42.75 20.4,44.19 D90.A 20.79,44.58 R302.1 ; v2(10.16,16.26) 10.16,15.65 13.72,12.09 45.62,12.09 47.24,13.72 52.96,13.72 54.1,12.57 54.99,12.57 55.88,11.68 70.36,11.68 70.99,12.32 70.99,14.86 70.42,15.43 69.87,15.43 68.48,16.82 68.48,24.92 v2(69.09,25.53)
CAN1_RX_M0_: length 1.1
  TOP w0.127: U32.4 19.43,44.34 v2(19.43,44.6)
  BOTTOM w0.127: D90.C 19.01,44.6 v2(19.43,44.6)
CAN1_STB_IO: length 3.4
  TOP w0.203: R301.2 12.44,41.4 13.54,40.31 U32.8
CAN1_TX_M0: length 115.8
  TOP w0.127: v2(10.16,16.89) 10.16,17.14 10.79,17.78 10.79,26.16 11.51,26.87 11.51,32.08 11.91,32.49 15.52,32.49 17.3,34.26 17.3,38.76 18.11,39.57 19,39.57 19.21,39.79 U32.1 ; M5.37 73.39,24.46 72.28,25.56 72.28,25.56 71.68,26.16 v2(69.09,26.16)
  BOTTOM w0.127: v2(10.16,16.89) 10.62,16.43 10.62,15.65 13.92,12.34 45.36,12.34 46.99,13.97 53.09,13.97 54.23,12.83 55.12,12.83 56.01,11.94 70.23,11.94 70.74,12.45 70.74,14.73 70.29,15.18 69.76,15.18 68.22,16.72 68.22,25.3 v2(69.09,26.16)
CAN1H: length 38.6
  TOP w0.203: v2(18.16,40.09) 18.12,40.13 17.61,40.13 15.9,38.42 15.9,34.74 14.81,33.66 11.38,33.66 10.34,32.61 10.34,27.3 8.7,25.65 v2(6.86,25.65)
  BOTTOM w0.127: L46.4 18.1,40.09 18.11,40.09 v2(18.16,40.09) 18.59,40.52 19.09,40.52 19.21,40.4 R304.1
  BOTTOM w0.254: v2(6.86,25.65) 6.86,25.78 6.48,26.16 6.48,27.51 ; 6.48,27.51 6.76,27.51 7.59,26.67 7.59,23.34 8.84,22.1 8.84,20.01 D89.1 6.49,19.17 F10.1 ; 6.48,27.51 D105.A
CAN1H_: length 7.4
  TOP w0.254: J39.5 5.46,21.15 5.21,20.9 v2(5.21,20.07)
  BOTTOM w0.254: v2(5.21,20.07) 5.21,19.15 4.95,18.9 F10.2 3.22,18.7 4.03,17.89 4.33,17.89 TP12.1
CAN1L: length 32.7
  TOP w0.203: v2(6.22,25.65) 6.73,26.16 8.74,26.16 10.01,27.43 10.01,32.75 11.24,33.99 14.68,33.99 15.57,34.88 15.57,38.56 17.91,40.89 v2(18.16,40.89)
  BOTTOM w0.127: L46.3 17.57,40.89 v2(18.16,40.89) 18.5,40.89 R303.1
  BOTTOM w0.254: v2(6.22,25.65) 6.22,25.26 6.48,25.01 D105.C 6.48,23.5 7.99,21.99 D89.2 6.49,21.07 F11.1
CAN1L_: length 6.6
  TOP w0.254: v2(4.65,20.07) 4.65,19.46 4.95,19.15 J39.4
  BOTTOM w0.254: TP13.1 3.17,22.46 3.22,22.42 F11.2 4.39,21.34 4.65,21.08 v2(4.65,20.07)
CAN2_H: length 1.9
  TOP w0.127: v2(15.01,36.3) 14.76,36.3 14.4,35.94 U33.7
  BOTTOM w0.127: L47.1 v2(15.01,36.3)
CAN2_L: length 1.8
  TOP w0.127: v2(15.02,37.1) 14.12,37.1 U33.6
  BOTTOM w0.127: L47.2 v2(15.02,37.1)
CAN2_RX_M0: length 94
  TOP w0.127: D107.A 23.24,38.48 23.67,38.05 v2(23.67,37.62) 23.67,35.38 24,35.05 33.2,35.05 v2(34.09,34.16) ; v2(54.86,37.97) 72.14,37.97 v2(73.03,37.08) ; v2(97.28,33.43) 97.66,33.81 97.66,40.63 97.06,41.24 M5.75
  BOTTOM w0.127: v2(34.09,34.16) 35.2,34.16 41.17,40.13 53.72,40.13 54.86,38.99 v2(54.86,37.97) ; R305.2 v2(23.67,37.62) ; v2(73.03,37.08) 73.42,37.08 73.67,37.34 82.55,37.34 86.23,33.66 97.05,33.66 v2(97.28,33.43)
CAN2_RX_M0_: length 4.1
  TOP w0.127: R306.2 22.25,37.56 21.33,38.48 D107.C U33.4
CAN2_STB_IO: length 1.9
  TOP w0.508: U33.8 12.78,34.67 12.7,34.75 R307.2
CAN2_TX_M0: length 89.3
  TOP w0.127: M5.74 97.06,40.24 97.27,40.03 v2(97.27,34.04) ; v2(54.86,37.34) 55.24,37.72 71.75,37.72 v2(72.39,37.08) ; v2(33.66,33.73) 32.72,34.67 v2(23.5,34.67) 23.38,34.79 Q15.2
  BOTTOM w0.127: v2(97.27,34.04) 97.14,33.91 86.36,33.91 82.68,37.59 72.9,37.59 v2(72.39,37.08) ; v2(23.5,34.67) 23.45,34.72 R308.2 ; v2(54.86,37.34) 54.47,37.73 54.47,39 53.59,39.88 41.27,39.88 35.13,33.73 v2(33.66,33.73)
CAN2_TX_M0_: length 4.2
  TOP w0.127: Q15.3 20.98,34.13 20.98,32.79 ; 20.98,32.79 19.21,34.56 U33.1 ; 20.98,32.79 R309.2
CAN2H: length 39
  TOP w0.203: v2(16.79,36.3) 16.73,36.24 16.73,34.39 15.2,32.87 14.85,32.87 11.68,32.87 11.1,32.28 11.1,26.97 10.11,25.98 v2(10.11,25.65)
  BOTTOM w0.127: R311.1 18.67,35.97 18.33,36.3 L47.4 v2(16.79,36.3)
  BOTTOM w0.254: F12.1 6.49,13.22 D91.1 7.99,13.84 9.22,15.06 9.22,16.84 11.23,18.85 11.23,20.73 10.92,21.03 10.92,27.31 10.63,27.6 D106.A 9.65,26.04 10.03,25.65 v2(10.11,25.65)
CAN2H_: length 6.7
  TOP w0.254: v2(5.21,14.22) 5.21,14.9 5.46,15.15 J39.2
  BOTTOM w0.254: v2(5.21,14.22) 5.21,13.77 5.21,13.21 4.95,12.95 F12.2 3.22,11.87 3.17,11.83 TP14.1
CAN2L: length 32.2
  TOP w0.203: v2(16.76,37.08) 16.36,36.68 16.36,36.12 16.4,36.09 16.4,34.53 15.06,33.2 11.55,33.2 10.77,32.42 10.77,27.15 9.63,26.01 9.63,25.07 v2(9.65,25.04)
  BOTTOM w0.127: R310.1 18.67,37.49 18.28,37.1 L47.3 16.78,37.1 v2(16.76,37.08)
  BOTTOM w0.254: v2(9.65,25.04) D106.C 9.65,21.51 9.42,21.29 9.42,17.68 8.69,16.94 8.69,15.82 D91.2 6.49,15.12 F13.1
CAN2L_: length 6.4
  TOP w0.254: v2(4.65,14.23) 4.65,13.46 4.95,13.15 J39.1
  BOTTOM w0.254: TP15.1 3.17,15.44 F13.2 4.39,15.39 4.65,15.14 v2(4.65,14.23)
CIF_CLKO_: length 110.7
  TOP w0.127: v2(22.66,62.99) 22.94,62.71 24.68,62.71 25.59,61.8 J28.9 ; v2(38.86,66.42) 38.61,66.17 38.61,62.41 39.14,61.87 66.19,61.87 69.47,65.15 75.44,65.15 77.34,63.25 78.18,63.25 78.2,63.23 78.52,63.23 78.54,63.25 84.45,63.25 85.85,61.85 85.85,41.17 v2(85.7,41.02)
  BOTTOM w0.127: v2(38.86,66.42) 38.86,68.33 37.97,69.22 37.34,69.22 36.07,70.48 28.45,70.48 23.62,65.66 23.62,64.06 22.66,63.1 v2(22.66,62.99) ; R143.2 C270.2 91.36,37.44 90.88,36.96 90.17,36.96 86.11,41.02 v2(85.7,41.02)
CIF_CLKOUT_SOC: length 3.4
  TOP w0.127: M5.71 95.35,37.24 v2(95,37.59)
  BOTTOM w0.127: v2(95,37.59) 94.47,37.07 93.64,37.07 93.27,37.44 R143.1
CIF_PDN0_: length 4.3
  TOP w0.127: R142.2 21.95,62.36 22.81,61.49 22.81,61.04 22.63,60.86 22.63,60.3 22.94,59.99 23.71,59.99 J28.6
CIF_RST: length 4.8
  TOP w0.127: J28.5 26.12,59.8 26.77,60.45 26.8,60.45 v2(27.18,60.83) 27.59,60.83 27.72,60.71 R377.2
  BOTTOM w0.127: R148.2 C146.2 26.7,60.35 v2(27.18,60.83)
CIF_RST_GPIO3_A3: length 53.8
  TOP w0.127: R377.1 30.33,60.71 33.33,57.7 53.05,57.7 54.2,58.85 55.42,58.85 55.76,59.19 56.5,59.19 56.62,59.31 v2(58.29,59.31) ; v2(67.18,71.12) 67.31,70.99 72.9,70.99 73.39,70.5 M5.124
  BOTTOM w0.127: v2(67.18,71.12) 67.18,68.2 v2(58.29,59.31)
EDP_HPD: length 6.4
  TOP w0.127: R88.2 54.74,9.69 J19.20
EDP_HPDIN_M1: length 48.7
  TOP w0.127: v2(54.08,13.74) 54.38,13.74 R88.1 ; v2(65.41,29.59) 62.48,29.59 57.39,24.5 M5.21
  BOTTOM w0.127: v2(65.41,29.59) 65.91,29.08 65.91,27.05 67.44,25.53 67.44,16.76 67.69,16.51 68.07,16.51 69.66,14.92 70.17,14.92 70.48,14.6 70.48,12.57 70.1,12.19 56.13,12.19 55.24,13.08 54.74,13.08 v2(54.08,13.74)
EDP_ON_: length 20.3
  TOP w0.127: v2(88.77,10.92) 90.04,10.92 90.68,10.29 90.68,8.38 89.92,7.62 86.77,7.62 J21.4
  BOTTOM w0.127: Q17.2 85.71,18.55 85.78,18.62 R380.2 86.23,17.8 86.15,17.72 R379.2 86.15,13.54 v2(88.77,10.92)
EDP_PWM4: length 69.3
  TOP w0.127: v2(66.04,29.59) 65.53,29.08 62.87,29.08 58.39,24.61 M5.22 ; v2(67.83,17.02) 67.96,17.14 70.99,17.14 71.53,16.61 U14.2 R89.1 ; v2(66.04,33.17) 65.94,33.07 52.22,33.07 51.89,33.4 v2(51.05,33.4)
  BOTTOM w0.127: v2(67.83,17.02) 67.83,25.64 66.42,27.05 66.42,29.21 v2(66.04,29.59) v2(66.04,33.17) ; v2(51.05,33.4) 51.05,37.39 50.34,38.1 42.04,38.1 38.73,34.8 38.73,33.1 R108.1
EDP_PWM4_: length 21.2
  TOP w0.127: v2(71.88,11.16) 71.88,11.18 70.87,12.19 70.87,12.76 U14.4 70.88,13.34 71.13,13.59 R89.2
  BOTTOM w0.127: J21.3 83.36,5.38 82.8,4.83 77.98,4.83 76.71,6.1 76.71,10.67 76.2,11.18 71.89,11.18 v2(71.88,11.16)
EDP_TX_AUXN: length 46.1
  TOP w0.102: v2(60.45,15.24) 60.73,15.52 61.42,15.52 61.52,15.42 61.52,15.22 C99.2 ; M5.197 35.97,31.88 36.43,31.88 v2(36.64,32.09)
  VCC w0.102: v2(36.64,32.09) 35.9,32.09 33.1,29.29 33.1,20.32 36.32,17.09 43.56,17.09 44.2,16.46 57.58,16.46 58.6,15.45 60.25,15.45 v2(60.45,15.24)
EDP_TX_AUXN_: length 8.2
  TOP w0.102: J19.15 61.29,8.36 61.39,8.26 61.91,8.26 62.13,8.48 62.13,10.64 61.75,11.02 61.75,11.86 R374.2 61.42,12.27 61.8,12.65 61.8,13.72 C99.1
EDP_TX_AUXP: length 46
  TOP w0.102: M5.198 36.02,31.65 36.36,31.65 v2(36.64,31.37) ; v2(60.45,15.96) 60.66,15.75 61.52,15.75 62.23,15.03 C100.2
  VCC w0.102: v2(36.64,31.37) 36.23,31.78 36.02,31.78 33.4,29.16 33.4,20.45 36.45,17.4 43.69,17.4 44.32,16.76 57.71,16.76 58.72,15.75 60.25,15.75 v2(60.45,15.96)
EDP_TX_AUXP_: length 8.2
  TOP w0.102: J19.16 61.29,7.31 62.36,8.38 62.36,10.74 61.98,11.12 61.98,11.76 R375.1 62.48,12.29 62.03,12.75 62.03,13.72 C100.1
EDP_TX_D0N: length 43.8
  TOP w0.102: M5.203 35.94,25.91 36.43,25.91 v2(36.64,26.12) ; v2(68.6,13.82) 68.76,13.66 68.76,13.39 68.53,13.16 C105.2
  VCC w0.102: v2(36.64,26.12) 36.54,26.02 36.05,26.02 35.56,25.53 35.56,22.43 37.92,20.07 46.36,20.07 47.12,19.3 58.88,19.3 59.64,18.54 63.25,18.54 66.55,15.24 67.82,15.24 68.81,14.25 68.81,14.03 v2(68.6,13.82)
EDP_TX_D0N_: length 6.6
  TOP w0.102: C105.1 68.85,11.88 68.85,11.16 70.23,9.78 70.23,8.71 70.23,8.7 70.23,8.39 70.1,8.26 69.78,8.26 69.66,8.13 69.51,8.13 69.29,8.36 J19.7
EDP_TX_D0P: length 43.7
  TOP w0.102: C106.2 69.19,13.16 68.99,13.35 68.99,13.62 69.19,13.82 v2(69.32,13.82) ; v2(36.64,25.4) 36.38,25.65 36.02,25.65 M5.204
  VCC w0.102: v2(36.64,25.4) 36.32,25.72 36.18,25.72 35.86,25.4 35.86,22.56 38.05,20.37 46.48,20.37 47.24,19.61 59,19.61 59.77,18.85 63.37,18.85 66.67,15.54 67.94,15.54 69.11,14.38 69.11,14.03 v2(69.32,13.82)
EDP_TX_D0P_: length 6.6
  TOP w0.102: C106.1 69.08,11.88 69.08,11.26 70.46,9.88 70.46,8.8 70.46,8.8 70.46,8.29 70.2,8.03 69.88,8.03 69.29,7.44 J19.8
EDP_TX_D1N: length 45.6
  TOP w0.102: v2(36.64,28.15) 36.3,27.81 36.03,27.81 M5.201 ; v2(66.47,13.84) 66.55,13.76 66.55,13.41 C103.2
  VCC w0.102: v2(36.64,28.15) 36.56,28.07 35.05,28.07 34.75,27.76 34.75,21.97 37.47,19.25 45.64,19.25 46.41,18.49 58.42,18.49 59.18,17.73 62.79,17.73 66.09,14.43 66.47,14.43 66.67,14.23 66.67,14.05 v2(66.47,13.84)
EDP_TX_D1N_: length 6.5
  TOP w0.102: J19.9 67.29,8.36 67.5,8.15 67.64,8.15 67.75,8.26 67.95,8.26 68.2,8.51 68.2,9.91 66.71,11.39 66.71,11.88 C103.1
EDP_TX_D1P: length 45.6
  TOP w0.102: v2(67.18,13.84) 66.8,13.46 66.8,13.34 66.98,13.16 C104.2 ; M5.202 35.95,27.58 36.49,27.58 v2(36.64,27.43)
  VCC w0.102: v2(67.18,13.84) 66.98,14.05 66.98,14.35 66.6,14.73 66.22,14.73 62.92,18.03 59.31,18.03 58.55,18.8 46.53,18.8 45.77,19.56 37.59,19.56 35.05,22.1 35.05,27.64 35.18,27.76 36.31,27.76 v2(36.64,27.43)
EDP_TX_D1P_: length 6.5
  TOP w0.102: C104.1 66.94,11.88 66.94,11.49 68.43,10 68.43,8.41 68.04,8.03 67.85,8.03 67.29,7.47 J19.10
EDP_TX_D2N: length 46.9
  TOP w0.102: v2(64.31,13.84) 64.52,13.63 64.52,13.51 C101.2 ; M5.199 36,29.84 36.43,29.84 v2(36.64,30.05)
  VCC w0.102: v2(36.64,30.05) 35.51,30.05 33.91,28.45 33.91,21.54 37.03,18.41 44.27,18.41 45.09,17.6 58.04,17.6 58.8,16.84 62.41,16.84 64.51,14.73 64.51,14.05 v2(64.31,13.84)
EDP_TX_D2N_: length 6.5
  TOP w0.102: J19.11 65.29,8.23 65.39,8.13 65.59,8.13 66.17,8.71 66.17,9.65 64.58,11.24 64.58,11.88 C101.1
EDP_TX_D2P: length 46.9
  TOP w0.102: C102.2 64.87,13.16 64.77,13.26 64.77,13.59 v2(65.02,13.84) ; M5.200 35.96,29.59 36.38,29.59 v2(36.64,29.34)
  VCC w0.102: v2(65.02,13.84) 64.82,14.05 64.82,14.86 62.53,17.14 58.93,17.14 58.17,17.91 45.21,17.91 44.4,18.72 37.16,18.72 34.21,21.67 34.21,28.32 35.64,29.75 36.33,29.75 36.43,29.65 36.43,29.54 v2(36.64,29.34)
EDP_TX_D2P_: length 6.4
  TOP w0.102: J19.12 65.29,7.5 66.4,8.61 66.4,9.75 64.81,11.33 64.81,11.88 C102.1
EDP_TX_D3N: length 49
  TOP w0.102: v2(36.64,34.12) 36.43,33.91 35.94,33.91 M5.195 ; v2(59.31,13.97) 59.51,13.77 59.51,13.53 C97.2
  VCC w0.102: v2(36.64,34.12) 36.56,34.04 35.89,34.04 32.21,30.35 32.21,19.35 35.56,16 42.8,16 43.43,15.37 57.15,15.37 58.17,14.35 59.34,14.35 59.44,14.25 59.44,14.11 v2(59.31,13.97)
EDP_TX_D3N_: length 6.1
  TOP w0.102: J19.17 59.29,8.28 59.39,8.18 59.67,8.18 60.2,8.71 60.2,10.03 59.55,10.68 59.55,11.88 C97.1
EDP_TX_D3P: length 49
  TOP w0.102: M5.196 36.03,33.66 36.38,33.66 v2(36.64,33.4) ; v2(60.03,13.97) 59.74,13.68 59.74,13.29 59.87,13.16 C98.2
  VCC w0.102: v2(60.03,13.97) 59.75,14.25 59.75,14.38 59.47,14.66 58.29,14.66 57.28,15.67 43.56,15.67 42.93,16.31 35.69,16.31 32.51,19.48 32.51,30.23 36.02,33.73 36.31,33.73 v2(36.64,33.4)
EDP_TX_D3P_: length 6.1
  TOP w0.102: J19.18 59.29,7.47 60.43,8.61 60.43,10.13 59.78,10.78 59.78,11.88 C98.1
EXT_EN: length 100.8
  TOP w0.127: v2(39.37,49.28) 49.53,49.28 50.29,48.51 50.29,48.29 50.32,48.27 50.32,26.66 48.44,24.79 44.35,24.79 43.39,23.83 M5.7 ; v2(52.48,79.1) 52.2,79.38 52.2,80.11 52.6,80.52 54.66,80.52 56.06,79.12 65.51,79.12 67.08,80.7 67.08,81.38 R16.1 ; v2(39.37,60.2) v2(49.61,60.2)
  BOTTOM w0.127: v2(49.61,60.2) 49.61,76.07 52.48,78.94 v2(52.48,79.1) ; v2(39.37,49.28) v2(39.37,60.2)
FE2.1_DM0: length 3.1
  BOTTOM w0.127: U8.29 86.39,62.62 86.51,62.5 86.73,62.5 87.02,62.79 87.02,63.15 87.3,63.42 87.5,63.42 R51.1
FE2.1_DM1: length 23.3
  TOP w0.127: v2(78.59,78.74) 78.35,78.98 78.35,79.22 78.07,79.49 76.95,79.49 76.25,78.79 75.11,78.79 74.68,79.23 74.68,79.52 L8.2
  BOTTOM w0.127: v2(78.59,78.74) 78.36,78.98 78.36,79.45 78.74,79.83 80.34,79.83 81.25,78.91 81.25,78.53 81.13,78.41 81.13,78.03 81.25,77.9 81.25,77.52 81.13,77.39 81.13,77.01 81.25,76.88 81.25,76.5 81.13,76.37 81.13,75.99 81.25,75.87 81.25,71.32 81.13,71.19 81.13,70.81 81.25,70.68 81.25,70.3 81.13,70.18 81.13,69.8 81.25,69.67 81.25,69.29 81.13,69.16 81.13,68.78 81.25,68.65 81.25,68.27 81.13,68.14 81.13,67.76 81.25,67.64 81.25,67.26 81.13,67.13 U8.18
FE2.1_DM1_: length 10.9
  TOP w0.127: J8.11 70.74,88.7 70.31,88.26 70.31,87.81 71.25,86.87 72.9,86.87 74.33,85.43 74.33,85.03 74.46,84.91 D18.6 D18.5 74.46,83.04 74.33,82.91 74.33,82.74 74.63,82.45 74.63,81.96 74.92,81.66 L8.3
FE2.1_DM2: length 23.6
  TOP w0.127: v2(79.38,78.62) 79.62,78.87 87.25,78.87 87.88,79.5 87.88,80.14 88.18,80.44 L9.2
  BOTTOM w0.127: v2(79.38,78.62) 79.62,78.87 79.88,78.87 80.01,78.74 80.01,70.98 80.26,70.74 80.26,67.26 80.13,67.13 U8.16
FE2.1_DM2_: length 12
  TOP w0.127: L9.3 87.88,82.53 87.88,82.8 88.06,82.98 88.06,83.44 88.2,83.57 D21.2 D21.9 88.2,85.21 88.07,85.33 88.07,86.53 86.74,87.86 86.74,89.66 87.25,90.17 88.01,90.17 88.67,90.83 88.67,91.21 88.8,91.34 J9.2
FE2.1_DM3: length 25.9
  TOP w0.127: L10.2 90.01,80.03 89.74,79.76 89.74,79.45 87.99,77.7 78.48,77.7 v2(78.23,77.45)
  BOTTOM w0.127: U8.13 78.63,67.13 78.75,67.26 78.75,70.86 78.94,71.05 78.94,77.54 78.79,77.7 78.48,77.7 v2(78.23,77.45)
FE2.1_DM3_: length 7.9
  TOP w0.127: J9.11 88.85,88.7 88.62,88.47 88.62,87.78 89.57,86.83 89.57,85.33 89.7,85.21 D21.6 D21.5 89.7,83.56 89.57,83.44 89.57,83.27 89.74,83.11 89.74,82.6 90.01,82.33 L10.3
FE2.1_DM4: length 118.9
  TOP w0.127: L12.2 135.27,49.77 135,50.04 134.08,50.04 v2(133.84,49.79)
  BOTTOM w0.127: v2(133.84,49.79) 134.08,50.04 136.76,50.04 139.06,52.35 139.06,71.23 135,75.29 135,81.03 132.59,83.44 98.53,83.44 98.02,83.95 79.88,83.95 76.73,80.8 76.73,76.73 74.04,74.04 74.04,66.19 75.94,64.29 76.08,64.29 76.24,64.12 U8.11
FE2.1_DM4_: length 6.6
  TOP w0.127: J10.2 142.09,48.39 141.96,48.51 140.72,48.51 139.2,50.04 138.71,50.04 D25.1 138.17,49.77 L12.3
FE2.1_DM5: length 88.3
  TOP w0.127: L14.2 135.27,59.67 135,59.94 134.08,59.94 v2(133.84,59.7)
  BOTTOM w0.127: v2(133.84,59.7) 134.08,59.94 134.73,59.94 135,60.22 135,65.41 132.59,67.82 132.59,70.1 132.97,70.48 132.97,80.64 131.7,81.92 99.72,81.92 94.74,76.94 94.74,71.45 91.82,68.53 91.82,62.87 88.96,60 86.48,60 86.36,60.12 U8.34
FE2.1_DM5_: length 6.2
  TOP w0.127: L14.3 138.17,59.67 D28.1 138.71,59.94 139.2,59.94 139.99,59.16 141.86,59.16 141.99,59.03 J11.2
FE2.1_DM6: length 78.3
  TOP w0.127: v2(134.2,69.47) 133.95,69.71 133.95,69.85 134.08,69.98 135.13,69.98 135.4,69.7 L15.2
  BOTTOM w0.127: U8.32 86.64,61.13 86.76,61 88.86,61 91.16,63.3 91.16,68.91 93.98,71.73 93.98,77.22 99.44,82.68 132.08,82.68 133.99,80.77 133.99,69.68 v2(134.2,69.47)
FE2.1_DM6_: length 5.9
  TOP w0.127: L15.3 138.29,69.7 D31.1 138.84,69.98 140.81,69.98 141.09,69.7 141.83,69.7 141.96,69.57 J12.2
FE2.1_DM7: length 65.5
  TOP w0.127: v2(120.44,38.71) 120.52,38.71 120.8,38.43 120.8,38.25 120.7,38.15 R335.2
  BOTTOM w0.127: U8.37 84.13,56.83 84.01,56.7 84.01,56.45 85.6,54.86 85.6,53.87 82.3,50.57 82.3,49.25 84.23,47.32 84.23,37.95 86.87,35.31 95.76,35.31 101.7,41.25 106.48,41.25 109.51,38.23 120.52,38.23 120.65,38.35 120.65,38.58 120.52,38.71 v2(120.44,38.71)
FE2.1_DM7_: length 5.4
  TOP w0.127: J41.36 123.05,35.03 123.33,35.31 123.33,35.57 122.7,36.2 121.03,36.2 120.73,36.5 120.73,36.83 R335.1
FE2.1_DP0: length 3.1
  BOTTOM w0.127: R50.1 87.5,63.17 87.4,63.17 87.27,63.04 87.27,62.69 86.83,62.25 86.53,62.25 86.41,62.12 U8.30
FE2.1_DP1: length 23.4
  TOP w0.127: v2(77.85,78.74) 78.1,78.98 78.1,79.11 77.97,79.24 77.06,79.24 76.36,78.54 75.01,78.54 74.42,79.12 74.42,79.47 L8.1
  BOTTOM w0.127: v2(77.85,78.74) 78.11,78.99 78.11,79.56 78.63,80.09 80.44,80.09 81.51,79.02 81.51,67.26 81.63,67.13 U8.19
FE2.1_DP1_: length 10.8
  TOP w0.127: J8.12 69.7,88.7 70.05,88.34 70.05,87.71 71.15,86.61 72.79,86.61 74.08,85.33 74.08,85.03 73.96,84.91 D18.7 D18.4 73.96,83.04 74.08,82.91 74.08,82.64 74.37,82.35 74.37,81.89 74.12,81.64 L8.4
FE2.1_DP2: length 23.5
  TOP w0.127: v2(79.38,79.37) 79.62,79.12 87.14,79.12 87.63,79.61 87.63,80.14 87.38,80.38 L9.1
  BOTTOM w0.127: v2(79.38,79.37) 79.62,79.12 79.99,79.12 80.26,78.85 80.26,71.09 80.51,70.84 80.51,67.26 80.63,67.13 U8.17
FE2.1_DP2_: length 12
  TOP w0.127: J9.3 88.29,91.34 88.42,91.21 88.42,90.94 87.91,90.42 87.14,90.42 86.49,89.77 86.49,87.76 87.82,86.42 87.82,85.33 87.7,85.21 D21.10 D21.1 87.7,83.55 87.81,83.44 87.81,83.08 87.63,82.9 87.63,82.48 L9.4
FE2.1_DP3: length 25.9
  TOP w0.127: v2(78.23,78.2) 78.48,77.95 87.88,77.95 89.48,79.56 89.48,79.76 89.21,80.03 L10.1
  BOTTOM w0.127: v2(78.23,78.2) 78.48,77.95 78.89,77.95 79.2,77.65 79.2,70.94 79.01,70.75 79.01,67.26 79.13,67.13 U8.14
FE2.1_DP3_: length 7.8
  TOP w0.127: J9.12 88.16,88.7 88.37,88.49 88.37,87.68 89.32,86.72 89.32,85.33 89.2,85.21 D21.7 D21.4 89.2,83.56 89.32,83.44 89.32,83.17 89.48,83 89.48,82.63 89.21,82.35 L10.4
FE2.1_DP4: length 117.2
  TOP w0.127: v2(133.84,50.54) 134.08,50.29 135,50.29 135.27,50.56 L12.1
  BOTTOM w0.127: U8.12 76.31,64.63 76.23,64.54 76.05,64.54 74.3,66.29 74.3,73.94 76.99,76.63 76.99,80.69 79.99,83.69 97.92,83.69 98.42,83.19 132.48,83.19 134.75,80.92 134.75,75.18 138.81,71.12 138.81,52.45 136.65,50.29 134.08,50.29 v2(133.84,50.54)
FE2.1_DP4_: length 6.6
  TOP w0.127: L12.4 138.17,50.56 D26.1 138.71,50.29 139.31,50.29 140.83,48.77 141.96,48.77 142.09,48.9 J10.3
FE2.1_DP5: length 87.4
  TOP w0.127: L14.1 135.27,60.47 135,60.2 134.08,60.2 v2(133.84,60.44)
  BOTTOM w0.127: U8.35 86.34,59.62 86.47,59.75 89.06,59.75 92.08,62.76 92.08,68.43 95,71.35 95,76.83 99.83,81.66 131.59,81.66 132.72,80.54 132.72,70.59 132.33,70.21 132.33,67.71 134.75,65.3 134.75,60.33 134.62,60.2 134.08,60.2 v2(133.84,60.44)
FE2.1_DP5_: length 6.2
  TOP w0.127: L14.4 138.17,60.47 D29.1 138.71,60.2 139.31,60.2 140.09,59.41 141.86,59.41 141.99,59.54 J11.3
FE2.1_DP6: length 78.3
  TOP w0.127: L15.1 135.4,70.5 135.13,70.23 133.98,70.23 133.7,69.96 133.7,69.71 v2(133.45,69.47)
  BOTTOM w0.127: U8.33 86.64,60.62 86.76,60.75 88.97,60.75 91.41,63.2 91.41,68.81 94.23,71.63 94.23,77.11 99.55,82.42 131.97,82.42 133.73,80.67 133.73,69.75 v2(133.45,69.47)
FE2.1_DP6_: length 5.9
  TOP w0.127: J12.3 141.96,70.08 141.83,69.95 141.2,69.95 140.92,70.23 138.84,70.23 D32.1 138.29,70.5 L15.4
FE2.1_DP7: length 65.8
  TOP w0.127: v2(121.18,38.71) 121.18,38.38 R336.2
  BOTTOM w0.127: U8.38 83.63,56.83 83.76,56.71 83.76,56.35 85.34,54.76 85.34,53.97 82.04,50.67 82.04,49.15 83.97,47.22 83.97,37.84 86.76,35.05 95.86,35.05 101.81,41 106.38,41 109.4,37.97 120.63,37.97 120.9,38.25 120.9,38.43 v2(121.18,38.71)
FE2.1_DP7_: length 5.4
  TOP w0.127: J41.38 123.85,35.03 123.58,35.31 123.58,35.68 122.81,36.45 121.14,36.45 120.98,36.61 120.98,36.86 R336.1
FE21_XIN: length 10
  BOTTOM w0.203: U8.22 83.13,67.31 84.15,68.33 R55.1 84.4,68.98 84.4,70.28 84.1,70.59 C64.2 84.1,73.79 83.73,74.15 XT1.1
FE21_XOUT: length 7.2
  BOTTOM w0.203: U8.23 83.63,67.22 85.01,68.6 R55.2 84.76,68.98 84.76,70.28 85.07,70.59 C65.2 85.07,72.15 XT1.3
GM_VDDIO:
  vias: v2(31.24,29.21) v2(31.55,28.83)
GMAC0_INT/PMEB_GPIO3_B0: length 26.7
  TOP w0.127: R215.2 96.93,77.22 v2(96.52,76.81) ; v2(93.61,68.12) 93.55,68.12 93.47,68.2 87.88,68.2 87.38,68.71 79.25,68.71 78.39,69.57 M5.119
  BOTTOM w0.127: v2(93.61,68.12) 93.61,68.46 95.89,70.74 95.89,76.17 v2(96.52,76.81)
GMAC0_MCLKINOUT: length 55.4
  TOP w0.127: v2(92.96,62.36) 94.11,61.21 94.11,53.72 92.33,51.94 92.33,51.47 91.69,50.84 91.69,40.51 92.2,40 92.2,38.48 91.69,37.97 91.69,29.34 90.17,27.81 90.17,24.75 90.2,24.72 90.2,24.32 90.39,24.13 M5.54
  BOTTOM w0.127: v2(92.96,62.36) 95.89,65.28 95.89,69.22 96.73,70.06 C171.2 R194.1 99.85,70.06 100.66,70.87 R193.1
GMAC0_MDC: length 66.1
  TOP w0.127: M5.55 91.39,24.26 91.19,24.46 91.19,24.77 90.68,25.27 90.68,27.56 92.2,29.08 92.2,37.72 92.71,38.23 92.71,40.89 92.2,41.4 92.2,50.63 92.84,51.26 92.84,51.71 93.96,52.83 v2(94.18,52.83)
  BOTTOM w0.127: U24.13 111.65,71.87 112.19,71.32 112.19,65.07 107.82,60.71 98.93,60.71 94.74,56.52 94.74,53.21 94.36,52.83 v2(94.18,52.83)
GMAC0_MDIO: length 65.4
  TOP w0.127: R220.1 109.85,71.49 v2(109.88,71.47) ; v2(94.26,51.97) 93.88,51.97 93.34,51.44 93.34,51.05 92.71,50.42 92.71,41.66 93.22,41.15 93.22,37.97 92.71,37.47 92.71,28.77 92.39,28.45 M5.56
  BOTTOM w0.127: U24.14 v2(109.88,71.47) 110.47,71.47 111.68,70.26 111.68,65.31 107.59,61.21 98.68,61.21 93.34,55.88 93.34,52.45 93.83,51.97 v2(94.26,51.97)
GMAC0_RSTN_GPIO3_A5: length 2.1
  TOP w0.127: M5.122 75.39,70.66 v2(75.06,70.99)
  BOTTOM w0.127: v2(75.06,70.99) 75.44,71.37 R219.1
GMAC0_RXCLK: length 55.7
  TOP w0.127: v2(88.44,53.75) 88.44,53.14 88.14,52.83 88.14,34.29 80.14,26.29 77.47,26.29 77.23,26.05 77.23,24.62 77.39,24.46 M5.41
  BOTTOM w0.127: v2(88.44,53.75) 88.44,54.41 89.15,55.12 89.15,55.63 90.42,56.9 90.42,59.8 91.97,61.34 92.96,61.34 96.9,65.28 98.6,65.28 C186.2 R227.2
GMAC0_RXD0: length 55.7
  TOP w0.127: v2(92.13,59.82) 92.28,59.82 93.09,59 93.09,54.23 91.31,52.45 91.31,52.07 90.68,51.44 90.68,30.23 87.5,27.05 87.5,25.78 86.39,24.67 M5.50
  BOTTOM w0.127: v2(92.13,59.82) 92.13,59.97 92.61,60.45 93.16,60.45 97.22,64.52 100.08,64.52 100.47,64.9 103.76,64.9 104.14,64.52 105.28,64.52 105.41,64.64 R223.2
GMAC0_RXD1: length 55.3
  TOP w0.127: M5.51 87.39,24.4 88.01,25.02 88.01,27.05 90.93,29.97 90.93,51.31 91.57,51.94 91.57,52.32 93.34,54.1 93.34,59.28 92.68,59.94 v2(92.68,59.97)
  BOTTOM w0.127: R224.2 106.4,65.1 105.56,64.26 104.03,64.26 103.65,64.64 100.57,64.64 100.19,64.26 97.33,64.26 93.26,60.2 92.91,60.2 v2(92.68,59.97)
GMAC0_RXD2: length 63.9
  TOP w0.127: v2(89.84,55.37) 88.65,55.37 87.38,54.1 87.38,34.65 79.78,27.05 76.96,27.05 76.07,26.16 76.07,25.27 75.39,24.59 M5.39
  BOTTOM w0.127: R225.2 107.44,65.18 106.27,64.01 103.93,64.01 103.55,64.39 100.68,64.39 100.3,64.01 97.43,64.01 92.83,59.41 91.54,59.41 90.93,58.8 90.93,56.64 90.17,55.88 90.17,55.7 v2(89.84,55.37)
GMAC0_RXD3: length 64.6
  TOP w0.127: M5.40 76.39,26.1 77.09,26.8 79.88,26.8 87.63,34.54 87.63,53.98 88.47,54.81 v2(89.76,54.81)
  BOTTOM w0.127: R226.2 108.46,65.69 106.52,63.75 103.82,63.75 103.44,64.14 100.78,64.14 100.4,63.75 97.54,63.75 92.94,59.16 91.67,59.16 91.19,58.67 91.19,56.52 90.42,55.75 90.42,55.35 89.89,54.81 v2(89.76,54.81)
GMAC0_RXDV_CRS: length 54.4
  TOP w0.127: M5.52 88.39,26.92 91.19,29.72 91.19,51.18 91.82,51.82 91.82,52.2 93.6,53.98 93.6,59.69 92.79,60.5 v2(92.1,60.5)
  BOTTOM w0.127: R228.2 103.94,65.1 103.89,65.15 100.36,65.15 99.98,64.77 97.12,64.77 93.18,60.83 92.43,60.83 v2(92.1,60.5)
GMAC0_TXCLK: length 5.4
  TOP w0.127: v2(82.17,25.27) 81.28,25.27 80.39,24.38 M5.44
  BOTTOM w0.127: v2(82.17,25.27) 82.17,25.02 82.42,24.76 82.42,24.59 C493.2 82.93,24.18 R205.1
GMAC0_TXCLK_: length 62.5
  TOP w0.127: v2(91.82,58.15) 91.44,57.77 91.44,56.39 91.82,56.01 91.82,54.86 90.04,53.09 90.04,52.7 89.41,52.07 89.41,33.63 88.39,32.62 88.39,32.38 v2(82.42,26.42)
  BOTTOM w0.127: R205.2 C174.2 82.55,26.88 82.42,26.75 v2(82.42,26.42) ; U24.20 109.43,69.07 109.73,68.77 109.73,68.2 109.35,67.82 109.35,65.84 106.75,63.25 103.61,63.25 103.23,63.63 100.99,63.63 100.61,63.25 97.92,63.25 93.22,58.55 92.43,58.55 92.03,58.15 v2(91.82,58.15)
GMAC0_TXD0: length 2.2
  TOP w0.127: v2(83.82,25.1) 83.39,24.66 M5.47
  BOTTOM w0.127: R197.1 83.82,25.1 v2(83.82,25.1)
GMAC0_TXD0_: length 62.6
  TOP w0.127: v2(92.41,57.33) 92.02,56.95 92.02,56.57 92.33,56.26 92.33,54.61 90.55,52.83 90.55,52.45 89.92,51.82 89.92,31.62 84.25,25.96 v2(83.82,25.96)
  BOTTOM w0.127: v2(92.41,57.33) 92.43,57.35 93.29,57.35 98.17,62.23 100.67,62.23 101.31,62.87 102.92,62.87 103.3,62.48 107.06,62.48 110.41,65.83 110.41,69.04 109.58,69.87 U24.18 ; R197.2 v2(83.82,25.96)
GMAC0_TXD1: length 2.3
  TOP w0.127: M5.48 84.39,24.55 v2(84.96,25.12)
  BOTTOM w0.127: v2(84.96,25.12) 84.99,25.1 R198.1
